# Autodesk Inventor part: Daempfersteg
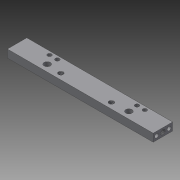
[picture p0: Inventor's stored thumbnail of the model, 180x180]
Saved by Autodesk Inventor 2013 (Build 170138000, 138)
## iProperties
Created: 2012-07
Part Number: Daempfersteg
Material: Allgemein
Document SubType Name: Modeling
Designer: rYan
Density: 1 g/cm^3
Mass: 2.75654 g
Surface Area: 25.2126 cm^2
Volume: 2.75654 cm^3
Author: rYan
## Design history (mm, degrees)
sketch "Skizze1"
  geometry: L1 (-37.5, -5)-(37.5, -5); L2 (37.5, -5)-(37.5, 5); L3 (37.5, 5)-(-37.5, 5); L4 (-37.5, 5)-(-37.5, -5); L5 (0, 7)-(0, -7) reference; L6 (-52.5, 0)-(52.5, 0) reference; 1 further point
  constraints: 8 end point, 2 parallel, 1 horizontal, 1 perpendicular, 2 other
  dimensions: "d0" = 75 distance of L2.end L3.end; "d2" = 10 distance of L3.end L1.start
extrude "Extrusion1" new body sketch "Skizze1" distance "d3" = 4; taper "d4" = 0 deg
sketch "Skizze9"
  geometry: L1 (-4, 0)-(-4, 10) reference; L2 (0, 0)-(0, 10) reference; L3 (-4, 5)-(0, 5); 1 further point
  constraints: 3 midpoint, 2 end point
hole "Bohrung4" sketch "Skizze9" at (-2, 5) diameter "d42" = 2.459; stored, may be unused: countersink angle "d46" = 90 deg, drill point angle "d48" = 118 deg; dims "d43" = 5, "d44" = 4, "d45" = 2, "d47" = 6
sketch "Skizze12"
  geometry: L1 (0, 0)-(0, 10) reference; L2 (0, 10)-(-4, 10) reference; L3 (-4, 0)-(-4, 10) reference; L4 (0, 0)-(-4, 0) reference; L5 (-2, 10)-(-2, 0); L6 (-4, 5)-(0, 5); C1 r 1.23 at (-2, 5) reference; 2 further points
  constraints: 4 end point, 3 midpoint, 2 point on line, 1 perpendicular, 1 symmetric about line
  dimensions: "d79" = 1.8 distance from line of L2 point (-2, 8.2)
hole "Bohrung7" sketch "Skizze12" at (-2, 8.2), (-2, 1.8) diameter "d80" = 2; stored, may be unused: countersink angle "d84" = 90 deg, drill point angle "d86" = 118 deg; dims "d81" = 6, "d82" = 4, "d83" = 2, "d85" = 3
node "Bohrungsspiegel"
mirror "Spiegeln3"
workplane "Arbeitsebene2"
node "Versenkungsspiegel"
  workplane "Arbeitsebene3"
sketch "Skizze7"
  geometry: L1 (-21.5, 5.14)-(-21.5, -4.928); L2 (20.5, 5.034)-(20.5, -5.034); L3 (0, -7.069)-(0, 7.175) reference; L4 (37.5, -5)-(-37.5, -5) reference; L5 (37.5, 5)-(37.5, -5) reference; L6 (-37.5, 5)-(37.5, 5) reference; L7 (-37.5, -5)-(-37.5, 5) reference; 3 further points
  constraints: 4 end point, 2 point on line
  dimensions: "d70" = 42 distance between parallel lines of L2 L1; "d72" = 3.5 distance from line of L4 point (-21.5, -1.5); "d73" = 3.5 distance from line of point (20.5, -1.5) L4 (= d72); "d87" = 16 distance between parallel lines of L1 L7
hole "Bohrung3" sketch "Skizze7" diameter "d30" = 3.2; stored, may be unused: countersink angle "d34" = 90 deg, drill point angle "d36" = 118 deg; dims "d31" = 6, "d32" = 5.8, "d33" = 2.2, "d35" = 8
sketch "Skizze10"
  geometry: L1 (0, -7)-(0, 7) reference; L2 (-52.5, 0)-(52.5, 0) reference; L3 (-13, -2)-(13, -2); 1 further point
  constraints: 2 end point, 1 parallel, 1 symmetric about line
  dimensions: "d57" = 2 distance between parallel lines of L2 L3; "d58" = 26 distance of L3.start L3.end
hole "Bohrung5" sketch "Skizze10" at (-13, -2), (13, -2) diameter "d50" = 2.459; stored, may be unused: countersink angle "d54" = 90 deg, drill point angle "d56" = 118 deg; dims "d51" = 3, "d52" = 4, "d53" = 2, "d55" = 3
sketch "Skizze11"
  geometry: L1 (-52.5, 0)-(52.5, 0) reference; L2 (37.5, -5)-(-37.5, -5) reference; L3 (37.5, 5)-(37.5, -5) reference; L4 (-37.5, 5)-(37.5, 5) reference; L5 (-37.5, -5)-(-37.5, 5) reference; L6 (-25, 3.2)-(-19.5, 3.2); L7 (20, 3.2)-(24, 3.2); L8 (-37.5, 5)-(37.5, 5) reference; L9 (-37.5, -5)-(-37.5, 5) reference; L10 (-23, 5)-(-23, -1.271); L11 (37.5, 5)-(37.5, -5) reference; L12 (22, 5)-(22, -1.062); C1 r 1.6 at (-21.5, -1.5) reference; C2 r 1.6 at (20.5, -1.5) reference; C3 r 1.23 at (-13, -2) reference; C4 r 1.23 at (13, -2) reference; C5 r 2.9 at (-21.5, -1.5) reference; C6 r 2.9 at (20.5, -1.5) reference; 2 further points
  constraints: 8 end point, 2 parallel, 2 point on line, 2 symmetric about line
  dimensions: "d74" = 1.8 distance between parallel lines of L4 L6; "d75" = 4 distance of point (-21, 3.2) L6.start; "d76" = 1.8 distance between parallel lines of L4 L7 (= d74); "d77" = 4 distance of L7.end L7.start (= d75); "d88" = 1.5 distance from line of C1.centre L10; "d89" = 1.5 distance from line of C2.centre L12
hole "Bohrung6" sketch "Skizze11" diameter "d63" = 2.1; stored, may be unused: countersink angle "d67" = 90 deg, drill point angle "d69" = 118 deg; dims "d64" = 6, "d65" = 4, "d66" = 2, "d68" = 8
node "Volumenkörper1"
node "Projizierte Kontur1"
node "Projizierte Kontur2"
node "Projizierte Kontur3"
other parameters: "d26" = -13, "d29" = -10.5
